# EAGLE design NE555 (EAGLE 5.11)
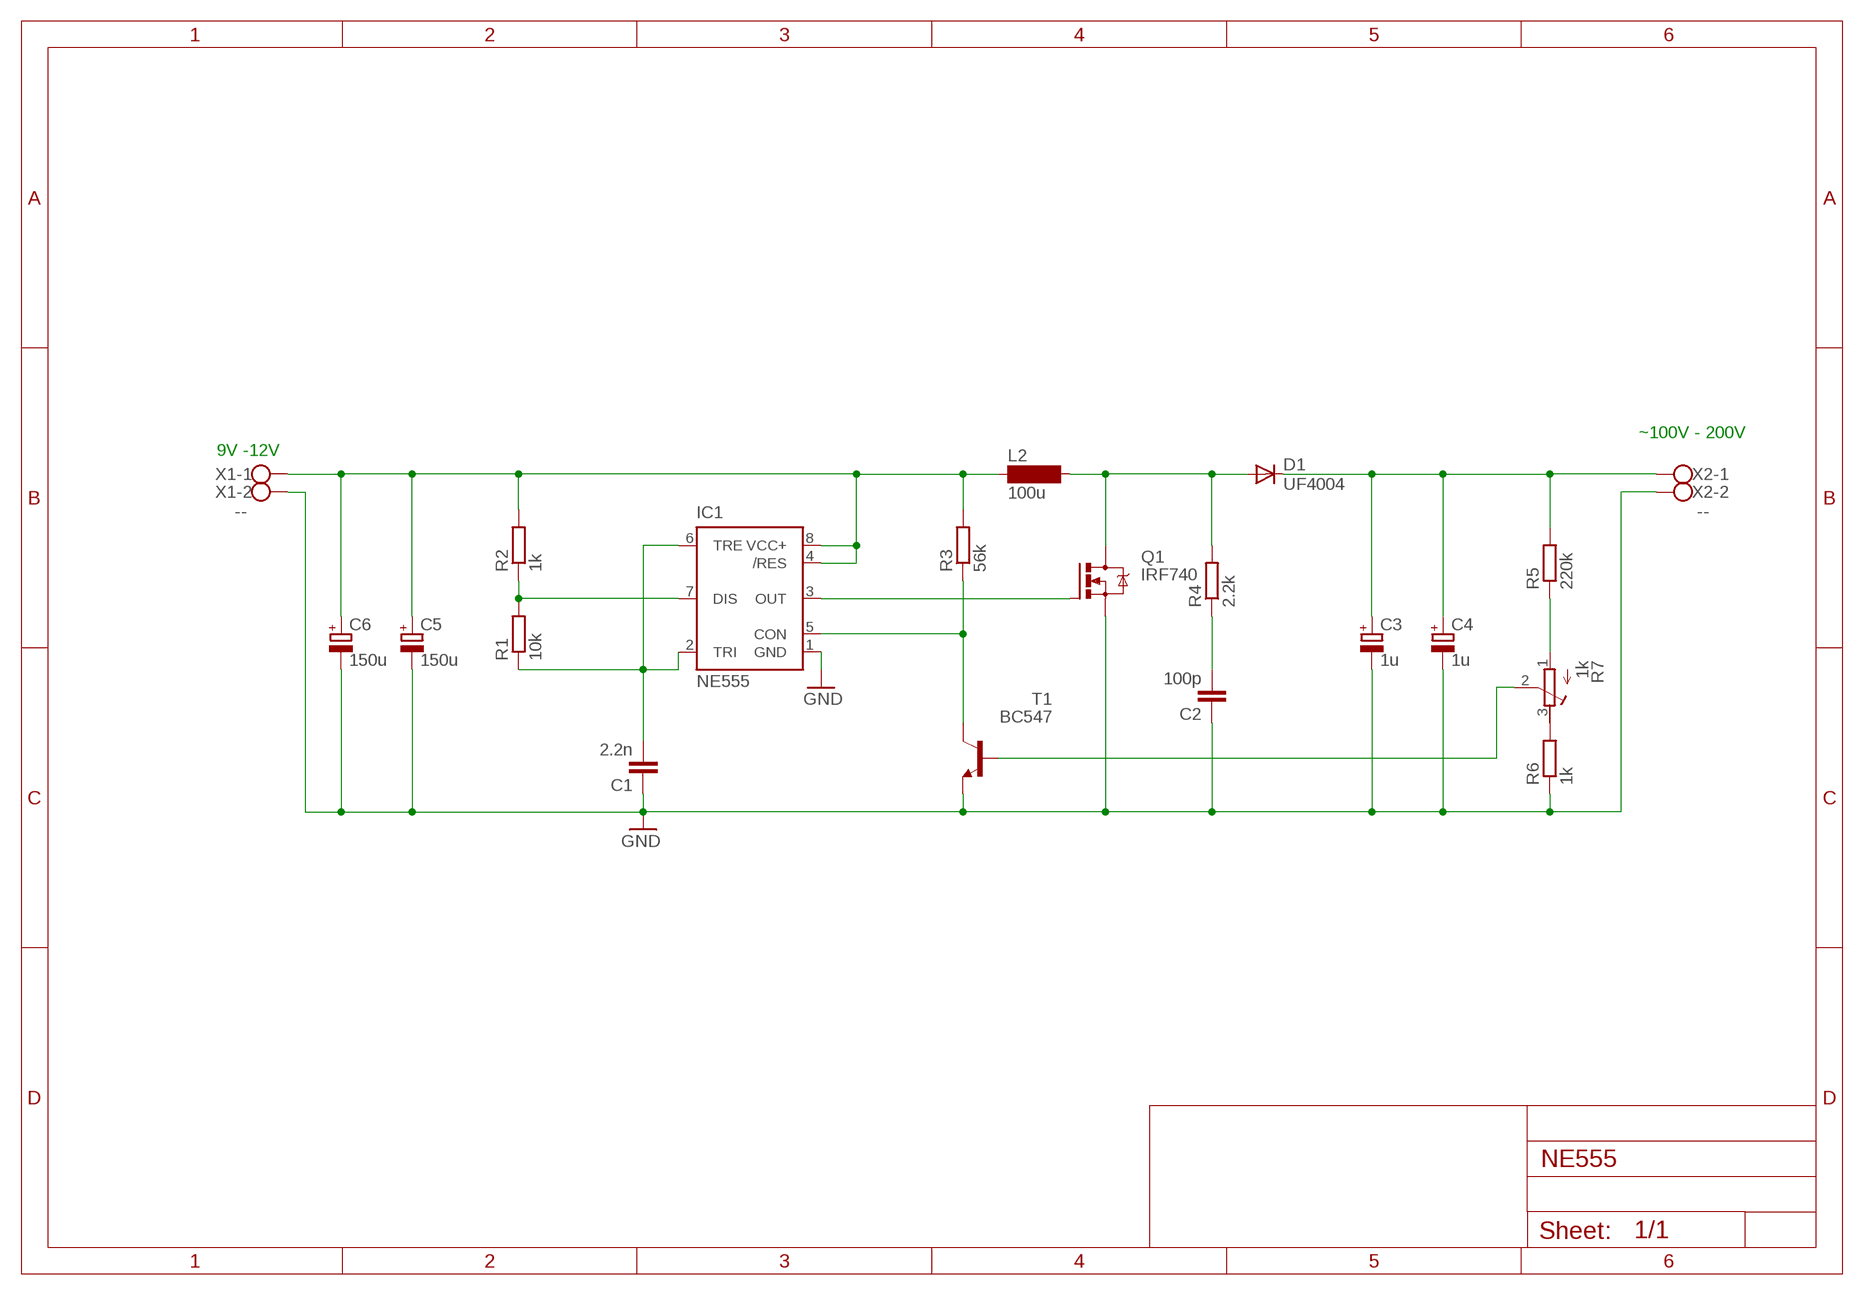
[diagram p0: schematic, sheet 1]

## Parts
C1  2.2n  C-EU025-030X050  [C025-030X050]
C2  100p  C-EU025-030X050  [C025-030X050]
C3  1u  CPOL-EUE2.5-6  [E2,5-6]
C4  1u  CPOL-EUE2.5-6  [E2,5-6]
C5  150u  CPOL-EUE15-9AXIAL  [E15-9]
C6  150u  CPOL-EUE15-9AXIAL  [E15-9]
D1  UF4004  1N4004  [DO41-10]
IC1  NE555  [DIL-08]
L2  100u  BS11  [BS11]
Q1  IRF740  [TO220BV]
R1  10k  R-EU_0207/7  [0207/7]
R2  1k  R-EU_0207/7  [0207/7]
R3  56k  R-EU_0207/7  [0207/7]
R4  2.2k  R-EU_0207/7  [0207/7]
R5  220k  R-EU_0207/7  [0207/7]
R6  1k  R-EU_0207/7  [0207/7]
R7  1k  R-TRIMM3296W  [RTRIM3296W]
T1  BC547  [TO92]
X1  --  W237-102  [W237-102]
X2  --  W237-102  [W237-102]

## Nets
GND: C1.1 C2.1 C3.- C4.- C5.- C6.- IC1.1(GND) Q1.S R6.1 T1.1(E) X1.2 X2.2
N$1: IC1.7(DIS) R1.2 R2.1
N$2: C5.+ C6.+ IC1.4(/RES) IC1.8(VCC+) L2.1 R2.2 R3.2 X1.1
N$3: C1.2 IC1.2(TRI) IC1.6(TRE) R1.1
N$5: IC1.5(CON) R3.1 T1.3(C)
N$6: IC1.3(OUT) Q1.G
N$8: D1.A L2.2 Q1.D R4.2
N$9: C3.+ C4.+ D1.C R5.2 X2.1
N$10: C2.2 R4.1
N$12: R7.2(S) T1.2(B)
N$13: R5.1 R7.1(E)
N$14: R6.2 R7.3(A)

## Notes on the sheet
- ~100V - 200V
- 9V -12V

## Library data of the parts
C1 C2 = rcl:C-EU: CAPACITOR, European symbol
C3-C6 = resistor:CPOL-EU: POLARIZED CAPACITOR, European symbol
D1 = diode:1N4004: DIODE
IC1 = st-microelectronics:NE555: General purpose bipolar Timer; MF: Arrow Electronics; MPN: NE555N; OC_FARNELL: 1467742; OC_NEWARK: 89K1486
L2 = inductor-neosid:BS: INDUCTOR; OC_FARNELL: unknown; OC_NEWARK: unknown
Q1 = transistor-power:IRF740: N-CHANNEL MOS FET
R1-R6 = rcl:R-EU_: RESISTOR, European symbol
R7 = rcl:R-TRIMM: Trimm resistor
T1 = transistor:BC547: NPN TRANSISTOR
X1 X2 = con-wago-500:W237-102: WAGO SCREW CLAMP; MPN: 237-102; OC_FARNELL: unknown; OC_NEWARK: 70K9898

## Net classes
0 default: width 0.762 mm, drill 0.508 mm, clearance 0.127 mm

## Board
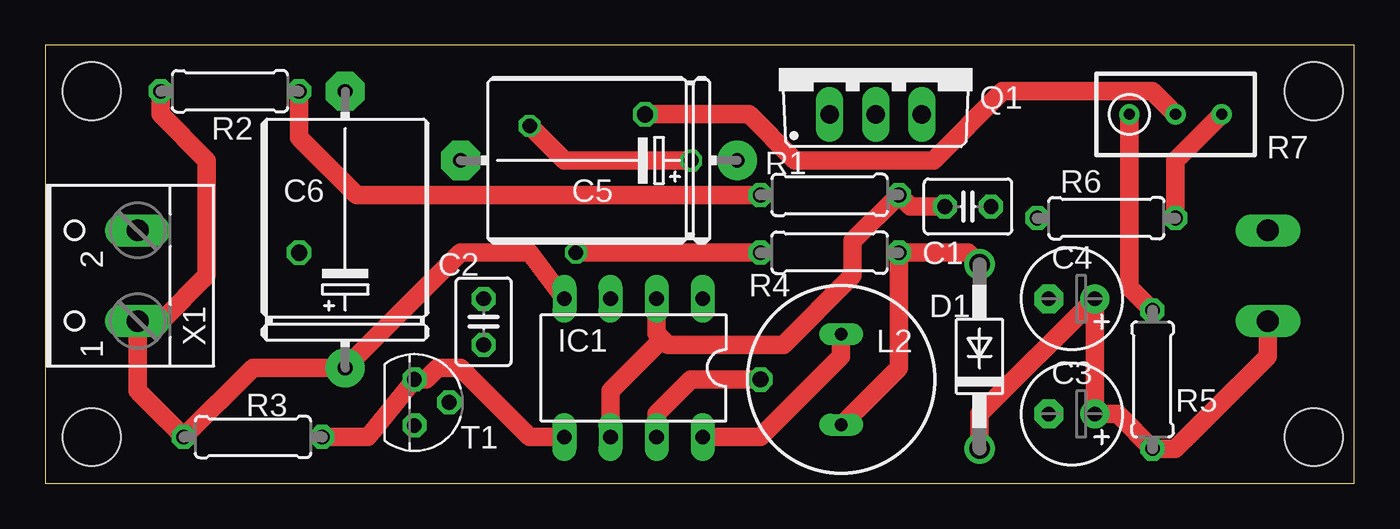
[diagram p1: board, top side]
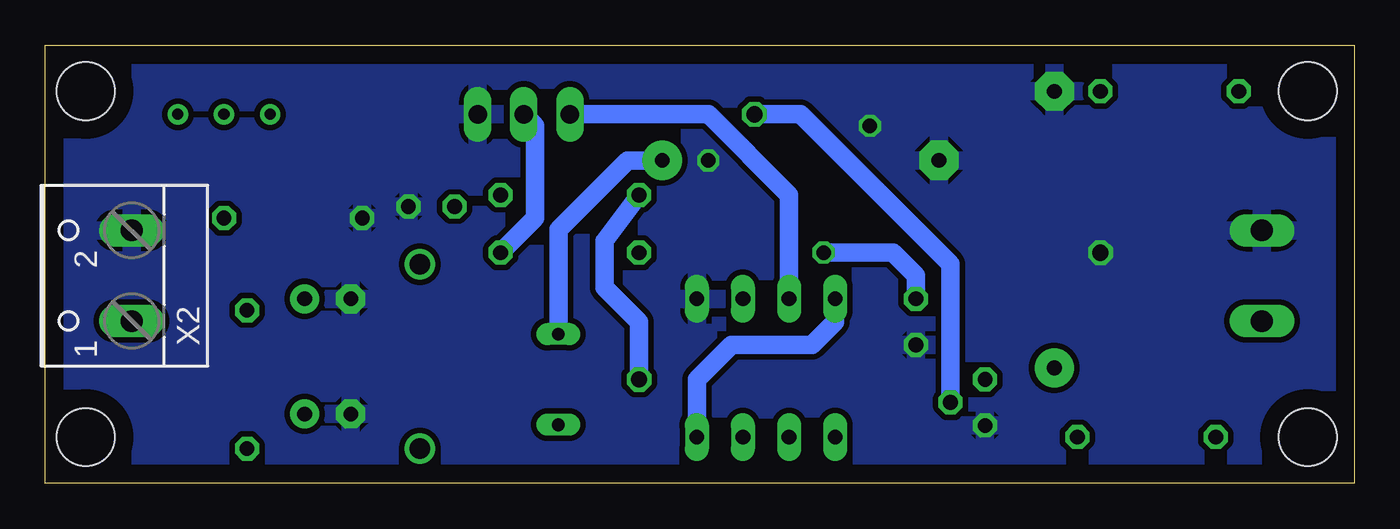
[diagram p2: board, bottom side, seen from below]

Size 72.06 x 24.12 mm. Coordinates in mm from the lower left corner, seen from the top.
Outline: 0,0 72.06,0 72.06,24.12 0,24.12 0,0
Copper layers (1*16): Top 0.035mm / dielectric 1.5mm / Bottom 0.035mm
Design rules "default": minimum track width 10mil, minimum drill 24mil, track to track 8mil, track to pad 8mil, pad to pad 8mil, via to via 8mil, smd to smd 8mil, copper to edge 40mil, drill to drill 8mil, minimum pad ring 10mil, minimum via ring 8mil, stop-mask expansion 4mil, vias tented up to drill 0mil, thermal gap 10mil
Holes 3.2 mm at 2.54,2.54 2.54,21.59 69.85,2.54 69.85,21.59

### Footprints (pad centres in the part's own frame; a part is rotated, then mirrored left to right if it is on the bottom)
C025-030X050 = drill 0.813 octagon: 1 -1.27,0; 2 1.27,0
E2,5-6 = drill 0.813 pad 1.6 round: + -1.27,0 | drill 0.813 pad 1.6 octagon: - 1.27,0
E15-9 = drill 0.813 pad 2.159 round: + -7.62,0 | drill 0.813 pad 2.159 octagon: - 7.62,0
DO41-10 = drill 1.118 round: A 5.08,0; C -5.08,0
DIL-08 = drill 0.813 long: 1 -3.81,-3.81; 2 -1.27,-3.81; 3 1.27,-3.81; 4 3.81,-3.81; 5 3.81,3.81; 6 1.27,3.81; 7 -1.27,3.81; 8 -3.81,3.81
BS11 = drill 0.7 long: 1 -2.5,0; 2 2.5,0
TO220BV = drill 1.016 long: D 0,-2.54; G -2.54,-2.54; S 2.54,-2.54
0207/7 = drill 0.813 octagon: 1 -3.81,0; 2 3.81,0
RTRIM3296W = drill 0.61 round: 1 0,-2.54; 2 0,0; 3 0,2.54
TO92 = drill 0.813 octagon: 1 1.27,0; 2 0,1.905; 3 -1.27,0
W237-102 = drill 1.194 long: 1 -2.5,-1.27; 2 2.5,-1.27

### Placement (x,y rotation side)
C1  50.8,15.24 180 top
C2  24.13,8.89 90 top
C3  56.52,3.81 180 top
C4  56.52,10.16 180 top
C5  30.48,17.78 180 top
C6  16.51,13.97 90 top
D1  51.44,6.99 90 top
IC1  32.38,6.35 180 top
L2  43.81,5.71 270 top
Q1  45.72,22.86 0 top
R1  43.18,15.88 180 top
R2  10.16,21.59 180 top
R3  11.43,2.54 180 top
R4  43.18,12.7 0 top
R5  60.96,5.71 270 top
R6  58.42,14.61 0 top
R7  62.23,20.32 270 top
T1  20.32,4.45 270 top
X1  3.81,11.43 90 top
X2  68.58,11.43 90 bottom

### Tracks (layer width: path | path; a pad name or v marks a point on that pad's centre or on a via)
GND  (via drill 0.8, 0.9 pad 0.61)
  Top 1.016: v35.56,17.78 28.57,17.78 v26.67,19.68
  other vias: 13.97,12.7
  pour Bottom (isolate 0.305): 0,24.13 0,0 72.39,0 72.39,24.13
N$1  (via drill 0.9 pad 0.61)
  Top 1.016: R2.1 13.97,19.05 17.14,15.88 R1.2 | IC1.7 33.66,3.81 35.56,5.71 v39.37,5.71
  Bottom 1.016: R1.2 41.27,13.34 41.27,10.79 39.37,8.89 v39.37,5.71
N$2
  Top 1.016: X1.1 5.08,5.08 R3.2 11.43,6.35 C6.+ 22.86,12.7 26.67,12.7 IC1.4 | X1.1 5.12,8.93 | X1.1 5.04,8.93 | R2.2 6.35,20.32 8.89,17.78 8.89,11.43 6.39,8.93 X1.1 | L2.1 43.81,6.99 39.37,2.54 IC1.8
  Bottom 1.016: C5.+ 40.01,17.78 43.81,13.97 L2.1 | IC1.8 36.2,5.71 34.29,7.62 29.84,7.62 28.57,8.89 IC1.4
N$3
  Top 1.016: C1.2 47.62,15.24 R1.1 44.45,13.34 44.45,11.43 40.64,7.62 34.29,7.62 33.97,7.94 | IC1.2 33.66,8.26 33.97,7.94 | IC1.6 31.11,5.08 33.97,7.94
N$5
  Top 1.016: R3.1 17.78,2.54 T1.3 20.95,5.71 21.59,6.35 22.86,6.35 26.67,2.54 IC1.5
N$6
  Bottom 1.016: Q1.G 35.56,20.32 31.11,15.88 IC1.3
N$8
  Top 1.016: L2.2 43.85,3.21 46.99,6.35 R4.2 50.8,12.7 D1.A
  Bottom 1.016: R4.2 45.09,14.61 45.09,19.68 Q1.D
N$9
  Top 1.016: X2.1 67.31,6.99 62.23,1.91 R5.2 59.05,3.81 C3.+ C4.+ 51.44,3.81 D1.C
N$10  (via drill 0.8 pad 0.61)
  Top 1.016: v29.21,12.7 R4.1
  Bottom 1.016: C2.2 24.13,11.43 25.4,12.7 v29.21,12.7
N$12  (via drill 0.9 pad 0.61)
  Top 1.016: R7.2 60.96,21.59 52.7,21.59 48.9,17.78 41.27,17.78 38.73,20.32 v33.02,20.32
  Bottom 1.016: T1.2 22.23,12.06 30.48,20.32 v33.02,20.32
N$13
  Top 1.016: R7.1 59.69,10.79 R5.1
N$14
  Top 1.016: R6.2 62.23,17.78 R7.3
